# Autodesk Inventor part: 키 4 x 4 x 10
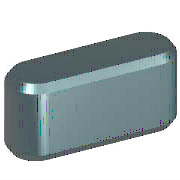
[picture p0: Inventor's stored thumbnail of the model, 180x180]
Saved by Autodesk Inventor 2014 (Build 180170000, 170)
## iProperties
IsCustomPart: 1
Created: 2012-02
Part Number: 키 4 x 4 x 10
Material: 강철, 연강
Description: 키 및 해당 키홈
Document SubType Name: Modeling
Standard: KS B 1311
Designer: mduedu
Standards Organization: KS
Language: ko-KR
Size Designation: 4 x 4 x 10
Categories: <MemberInstance><Categories><Category DisplayName="샤프트 부품" InternalName="7f7aeb1f-a693-4053-b835-cee3144e0d98" Mnemonic="SHFT"><Category DisplayName="키" Interna
Density: 1 g/cm^3
Appearance: Yellow
Author: mduedu
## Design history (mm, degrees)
sketch "스케치1"
  geometry: L1 (2, 2)-(8, 2); L2 (8, -2)-(2, -2); L3 (0, 9.4)-(0, -7.4) reference; L4 (-5, 0)-(30, 0) reference; L5 (10, 0)-(10, 7); A1 r 2 centre (2, 0) between (2, 2) and (2, -2); A2 r 2 centre (8, 0) between (8, -2) and (8, 2)
  constraints: 6 end point, 5 point on circle, 4 tangent, 3 point on line, 2 centre point, 1 horizontal, 1 parallel, 1 perpendicular
  dimensions: "d0" = 2 radius of A1 (= 0.5 x PB); "d13" = 2 radius of A2 (= 0.5 x PB); "d14" = 10 distance between parallel lines of L5 L3 (= NLG)
extrude "본체1" new body sketch "스케치1" taper "d3" = 0 deg; stored distance "d4" = 10
workplane "Work Plane3"
body "Solid1"
workplane "Work Plane1"
workplane "Work Plane2"
chamfer "모따기1" distance "d8" = 0.25 (= PHH); stored, may be unused: second distance "d9" = 0.25 (= PHH), angle "d15" = 45 deg
other parameters: "d1" = -2.5 (= -PNT), "d2" = 1.5 (= PH - PNT), "NLG" = 10 [user parameter; used in 3 equation terms], "PB" = 4 [user parameter; used in 2 equation terms], "PNT" = 2.5 [user parameter; used in 2 equation terms], "PH" = 4 [user parameter; used in 1 equation term], "PHH" = 0.25 [user parameter; used in 2 equation terms], "d10" = 0, "d16" = 0, "d17" = 0, "d18" = 0, "WDMAX" = 12 [user parameter], "RR" = 0.08 [user parameter], "PUEB" = 1.8 [user parameter]
